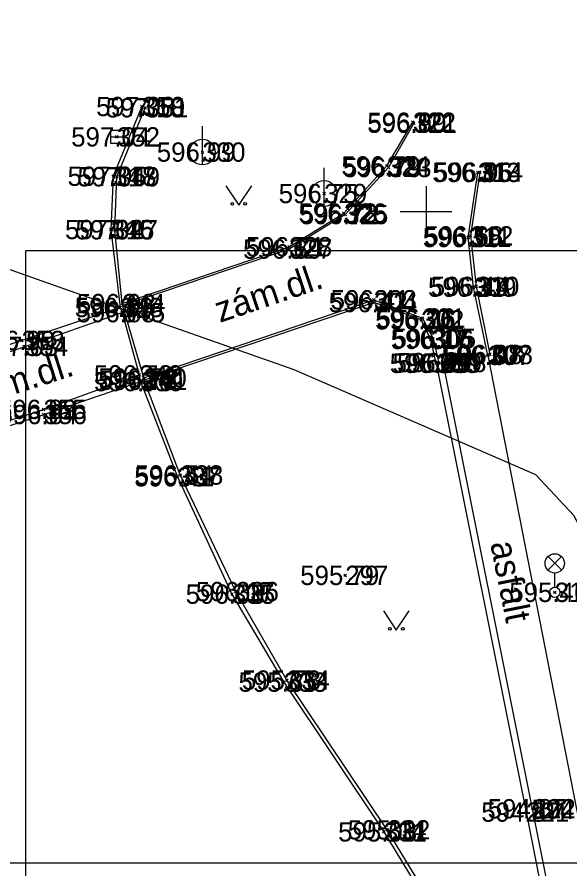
# Model space of a CAD drawing. Extents: x -844765 to -843273, y -997542 to -995529.
# Drawn here: x -843415.89 to -843394.41, y -997375.54 to -997342.43 of the extents above; entities that cross this region are included whole.
import ezdxf

# ---------------------------------------------------------------- set-up
doc = ezdxf.new("R2010")
doc.units = 0
for name, color, linetype in [('Betonový strop', 7, 'Continuous'), ('Dno', 7, 'Continuous'), ('Doplněk polohopisu', 7, 'Continuous'), ('Groma', 7, 'Continuous'), ('Osa', 7, 'Continuous'), ('Rámeček', 7, 'Continuous'), ('Sítě podzemní nerozlišené', 7, 'Continuous'), ('Vrstva 63', 7, 'Continuous'), ('Výška', 7, 'Continuous'), ('Číslo bodu', 7, 'Continuous'), ('Řezy', 7, 'Continuous')]:
    doc.layers.add(name, color=color, linetype=linetype)

msp = doc.modelspace()

# ---------------------------------------------------------------- linework, layer by layer
at = {"layer": 'Betonový strop'}
for p, q in [((-843399.33, -997355.86), (-843397.6, -997355.58)), ((-843397.6, -997355.58), (-843397.52, -997355.55))]:
    msp.add_line(p, q, dxfattribs=at)
for points in [[(-843411.04, -997345.91), (-843412.15, -997348.62), (-843412.25, -997350.69), (-843411.88, -997353.72), (-843411.81, -997353.92), (-843411.14, -997356.34), (-843411.1, -997356.6), (-843409.66, -997360.3), (-843407.54, -997364.86), (-843405.52, -997368.28), (-843401.64, -997374.1), (-843397.84, -997380.36), (-843394.46, -997387.21), (-843392.42, -997392.24)], [(-843392.47, -997391.81), (-843394.34, -997387.15), (-843397.7, -997380.27), (-843401.51, -997374.02), (-843405.41, -997368.2), (-843407.39, -997364.76), (-843409.55, -997360.23), (-843410.95, -997356.55), (-843410.97, -997356.46), (-843411.8, -997353.57), (-843412.09, -997350.7), (-843412.01, -997348.64), (-843410.91, -997345.96)], [(-843411.8, -997353.57), (-843405.32, -997351.36), (-843403.19, -997350.05), (-843401.52, -997348.22), (-843400.51, -997346.52)], [(-843400.48, -997346.56), (-843401.46, -997348.28), (-843403.14, -997350.11), (-843405.32, -997351.45), (-843411.778, -997353.647)], [(-843397.6, -997355.58), (-843398.16, -997352.93), (-843398.36, -997351), (-843397.99, -997348.47)], [(-843397.91, -997348.46), (-843398.28, -997350.94), (-843398.05, -997352.9), (-843397.52, -997355.55)], [(-843410.97, -997356.46), (-843402.03, -997353.42), (-843400.14, -997354.13), (-843399.73, -997354.92), (-843399.5, -997355.88)], [(-843399.61, -997355.89), (-843399.82, -997354.96), (-843400.19, -997354.2), (-843402.02, -997353.53), (-843410.95, -997356.55)], [(-843411.88, -997353.72), (-843415.71, -997355), (-843419.57, -997356.31)], [(-843419.54, -997356.54), (-843415.58, -997355.23), (-843411.81, -997353.92)], [(-843397.6, -997355.58), (-843394.16, -997373.22), (-843391.89, -997384.08), (-843391.57, -997385.85), (-843390.33, -997391.86), (-843386.25, -997412.31), (-843384.43, -997421.53), (-843384.06, -997423.53), (-843381.79, -997434.8)], [(-843399.61, -997355.89), (-843399.5, -997355.88), (-843399.33, -997355.86)], [(-843399.61, -997355.89), (-843396.11, -997373.33), (-843392.47, -997391.81), (-843392.42, -997392.24), (-843388.24, -997412.76), (-843386.27, -997422.84), (-843384.29, -997432.84)], [(-843384.04, -997432.8), (-843386.03, -997422.75), (-843388, -997412.68), (-843392.09, -997392.16), (-843395.86, -997373.2), (-843399.33, -997355.86)], [(-843418.65, -997358.89), (-843414.86, -997357.68), (-843411.14, -997356.34)], [(-843418.55, -997359.09), (-843414.85, -997357.88), (-843411.1, -997356.6)]]:
    msp.add_lwpolyline(points, dxfattribs=at)
at = {"layer": 'Dno'}
for points in [[(-843407.775, -997348.994), (-843407.275, -997349.744), (-843406.775, -997348.994)], [(-843401.655, -997365.509), (-843401.155, -997366.259), (-843400.655, -997365.509)]]:
    msp.add_lwpolyline(points, dxfattribs=at)
for centre in [(-843407.525, -997349.694), (-843407.025, -997349.694), (-843401.405, -997366.209), (-843400.905, -997366.209)]:
    msp.add_circle(centre, 0.05, dxfattribs=at)
at = {"layer": 'Doplněk polohopisu'}
for p, q in [((-843408.69, -997348.18), (-843408.69, -997346.68)), ((-843412.26, -997347.09), (-843411.76, -997347.09)), ((-843403.96, -997349.79), (-843403.96, -997348.29))]:
    msp.add_line(p, q, dxfattribs=at)
msp.add_lwpolyline([(-843412.26, -997347.34), (-843411.76, -997347.34), (-843411.76, -997346.84), (-843412.26, -997346.84)], close=True, dxfattribs=at)
for centre in [(-843408.69, -997347.68), (-843403.96, -997349.29)]:
    msp.add_circle(centre, 0.5, dxfattribs=at)
at = {"layer": 'Groma'}
for p, q in [((-843395.264, -997363.928), (-843394.736, -997363.4)), ((-843394.728, -997363.925), (-843395.256, -997363.396)), ((-843395, -997364.59), (-843395, -997364.04))]:
    msp.add_line(p, q, dxfattribs=at)
for centre, radius in [((-843395, -997363.665), 0.375), ((-843395, -997364.79), 0.2)]:
    msp.add_circle(centre, radius, dxfattribs=at)
at = {"layer": 'Osa'}
msp.add_lwpolyline([(-843361.41, -997525.395), (-843362.635, -997520.015), (-843367.895, -997475.79), (-843371.92, -997453.18), (-843393.72, -997362.81), (-843394.265, -997361.8), (-843395.735, -997360.23), (-843405.12, -997356.145), (-843414.51, -997352.845), (-843426.28, -997348.668), (-843434.95, -997345.635), (-843447.93, -997341.273), (-843467.555, -997334.81), (-843481.31, -997330.35), (-843488.74, -997327.355), (-843502.42, -997320.345)], dxfattribs=at)
at = {"layer": 'Rámeček'}
for p, q in [((-843400, -997349), (-843400, -997351)), ((-843399, -997350), (-843401, -997350))]:
    msp.add_line(p, q, dxfattribs=at)
at = {"layer": 'Sítě podzemní nerozlišené'}
for p, q in [((-843411.04, -997345.91), (-843411.09, -997345.86)), ((-843411.04, -997345.91), (-843411.09, -997345.96)), ((-843411.04, -997345.91), (-843410.99, -997345.86)), ((-843411.04, -997345.91), (-843410.99, -997345.96)), ((-843410.91, -997345.96), (-843410.96, -997345.91)), ((-843410.91, -997345.96), (-843410.86, -997345.91)), ((-843410.91, -997345.96), (-843410.96, -997346.01)), ((-843410.91, -997345.96), (-843410.86, -997346.01)), ((-843400.51, -997346.52), (-843400.56, -997346.47)), ((-843400.51, -997346.52), (-843400.56, -997346.57)), ((-843400.48, -997346.56), (-843400.53, -997346.51)), ((-843400.48, -997346.56), (-843400.53, -997346.61)), ((-843400.51, -997346.52), (-843400.46, -997346.47)), ((-843400.51, -997346.52), (-843400.46, -997346.57)), ((-843400.48, -997346.56), (-843400.43, -997346.51)), ((-843400.48, -997346.56), (-843400.43, -997346.61)), ((-843412.01, -997347.09), (-843412.06, -997347.04)), ((-843412.01, -997347.09), (-843412.06, -997347.14)), ((-843412.01, -997347.09), (-843411.96, -997347.04)), ((-843412.01, -997347.09), (-843411.96, -997347.14)), ((-843408.69, -997347.68), (-843408.74, -997347.63)), ((-843408.69, -997347.68), (-843408.74, -997347.73)), ((-843408.69, -997347.68), (-843408.64, -997347.63)), ((-843408.69, -997347.68), (-843408.64, -997347.73)), ((-843401.52, -997348.22), (-843401.57, -997348.17)), ((-843401.52, -997348.22), (-843401.57, -997348.27)), ((-843401.52, -997348.22), (-843401.47, -997348.17)), ((-843401.52, -997348.22), (-843401.47, -997348.27)), ((-843401.46, -997348.28), (-843401.51, -997348.23)), ((-843401.46, -997348.28), (-843401.41, -997348.23)), ((-843401.46, -997348.28), (-843401.51, -997348.33)), ((-843401.46, -997348.28), (-843401.41, -997348.33)), ((-843397.99, -997348.47), (-843398.04, -997348.42)), ((-843397.99, -997348.47), (-843398.04, -997348.52)), ((-843397.99, -997348.47), (-843397.94, -997348.42)), ((-843397.99, -997348.47), (-843397.94, -997348.52)), ((-843397.91, -997348.46), (-843397.96, -997348.41)), ((-843397.91, -997348.46), (-843397.96, -997348.51)), ((-843397.91, -997348.46), (-843397.86, -997348.41)), ((-843397.91, -997348.46), (-843397.86, -997348.51)), ((-843412.15, -997348.62), (-843412.2, -997348.57)), ((-843412.15, -997348.62), (-843412.2, -997348.67)), ((-843412.15, -997348.62), (-843412.1, -997348.57)), ((-843412.15, -997348.62), (-843412.1, -997348.67)), ((-843412.01, -997348.64), (-843412.06, -997348.59)), ((-843412.01, -997348.64), (-843412.06, -997348.69)), ((-843412.01, -997348.64), (-843411.96, -997348.59)), ((-843412.01, -997348.64), (-843411.96, -997348.69)), ((-843403.96, -997349.29), (-843404.01, -997349.24)), ((-843403.96, -997349.29), (-843404.01, -997349.34)), ((-843403.96, -997349.29), (-843403.91, -997349.24)), ((-843403.96, -997349.29), (-843403.91, -997349.34)), ((-843403.19, -997350.05), (-843403.24, -997350)), ((-843403.19, -997350.05), (-843403.24, -997350.1)), ((-843403.19, -997350.05), (-843403.14, -997350)), ((-843403.19, -997350.05), (-843403.14, -997350.1)), ((-843403.14, -997350.11), (-843403.19, -997350.06)), ((-843403.14, -997350.11), (-843403.19, -997350.16)), ((-843403.14, -997350.11), (-843403.09, -997350.06)), ((-843403.14, -997350.11), (-843403.09, -997350.16)), ((-843412.25, -997350.69), (-843412.3, -997350.64)), ((-843412.25, -997350.69), (-843412.3, -997350.74)), ((-843412.25, -997350.69), (-843412.2, -997350.64)), ((-843412.25, -997350.69), (-843412.2, -997350.74)), ((-843412.09, -997350.7), (-843412.14, -997350.65)), ((-843412.09, -997350.7), (-843412.14, -997350.75)), ((-843412.09, -997350.7), (-843412.04, -997350.65)), ((-843412.09, -997350.7), (-843412.04, -997350.75)), ((-843398.36, -997351), (-843398.41, -997350.95)), ((-843398.36, -997351), (-843398.41, -997351.05)), ((-843398.36, -997351), (-843398.31, -997350.95)), ((-843398.36, -997351), (-843398.31, -997351.05)), ((-843398.28, -997350.94), (-843398.33, -997350.89)), ((-843398.28, -997350.94), (-843398.33, -997350.99)), ((-843398.28, -997350.94), (-843398.23, -997350.89)), ((-843398.28, -997350.94), (-843398.23, -997350.99)), ((-843405.32, -997351.36), (-843405.37, -997351.31)), ((-843405.32, -997351.36), (-843405.37, -997351.41)), ((-843405.32, -997351.45), (-843405.37, -997351.4)), ((-843405.32, -997351.45), (-843405.37, -997351.5)), ((-843405.32, -997351.36), (-843405.27, -997351.31)), ((-843405.32, -997351.36), (-843405.27, -997351.41)), ((-843405.32, -997351.45), (-843405.27, -997351.4)), ((-843405.32, -997351.45), (-843405.27, -997351.5)), ((-843398.05, -997352.9), (-843398.1, -997352.85)), ((-843398.05, -997352.9), (-843398, -997352.85)), ((-843398.16, -997352.93), (-843398.21, -997352.88)), ((-843398.16, -997352.93), (-843398.21, -997352.98)), ((-843398.16, -997352.93), (-843398.11, -997352.88)), ((-843398.16, -997352.93), (-843398.11, -997352.98)), ((-843398.05, -997352.9), (-843398.1, -997352.95)), ((-843398.05, -997352.9), (-843398, -997352.95)), ((-843411.8, -997353.57), (-843411.85, -997353.52)), ((-843411.8, -997353.57), (-843411.75, -997353.52)), ((-843402.03, -997353.42), (-843402.08, -997353.37)), ((-843402.03, -997353.42), (-843402.08, -997353.47)), ((-843402.02, -997353.53), (-843402.07, -997353.48)), ((-843402.02, -997353.53), (-843402.07, -997353.58)), ((-843402.03, -997353.42), (-843401.98, -997353.37)), ((-843402.03, -997353.42), (-843401.98, -997353.47)), ((-843402.02, -997353.53), (-843401.97, -997353.48)), ((-843402.02, -997353.53), (-843401.97, -997353.58)), ((-843411.88, -997353.72), (-843411.93, -997353.67)), ((-843411.88, -997353.72), (-843411.93, -997353.77)), ((-843411.88, -997353.72), (-843411.83, -997353.67)), ((-843411.88, -997353.72), (-843411.83, -997353.77)), ((-843411.8, -997353.57), (-843411.85, -997353.62)), ((-843411.8, -997353.57), (-843411.75, -997353.62)), ((-843411.81, -997353.92), (-843411.86, -997353.87)), ((-843411.81, -997353.92), (-843411.86, -997353.97)), ((-843411.81, -997353.92), (-843411.76, -997353.87)), ((-843411.81, -997353.92), (-843411.76, -997353.97)), ((-843400.19, -997354.2), (-843400.24, -997354.15)), ((-843400.14, -997354.13), (-843400.19, -997354.08)), ((-843400.14, -997354.13), (-843400.19, -997354.18)), ((-843400.19, -997354.2), (-843400.14, -997354.15)), ((-843400.14, -997354.13), (-843400.09, -997354.08)), ((-843400.14, -997354.13), (-843400.09, -997354.18)), ((-843400.19, -997354.2), (-843400.24, -997354.25)), ((-843400.19, -997354.2), (-843400.14, -997354.25)), ((-843415.71, -997355), (-843415.76, -997354.95)), ((-843415.71, -997355), (-843415.76, -997355.05)), ((-843415.71, -997355), (-843415.66, -997354.95)), ((-843415.71, -997355), (-843415.66, -997355.05)), ((-843415.58, -997355.23), (-843415.63, -997355.18)), ((-843415.58, -997355.23), (-843415.53, -997355.18)), ((-843399.82, -997354.96), (-843399.87, -997354.91)), ((-843399.82, -997354.96), (-843399.87, -997355.01)), ((-843399.82, -997354.96), (-843399.77, -997354.91)), ((-843399.82, -997354.96), (-843399.77, -997355.01)), ((-843399.73, -997354.92), (-843399.78, -997354.87)), ((-843399.73, -997354.92), (-843399.78, -997354.97)), ((-843399.73, -997354.92), (-843399.68, -997354.87)), ((-843399.73, -997354.92), (-843399.68, -997354.97)), ((-843415.58, -997355.23), (-843415.63, -997355.28)), ((-843415.58, -997355.23), (-843415.53, -997355.28)), ((-843397.52, -997355.55), (-843397.57, -997355.5)), ((-843397.52, -997355.55), (-843397.47, -997355.5)), ((-843399.61, -997355.89), (-843399.66, -997355.84)), ((-843399.61, -997355.89), (-843399.56, -997355.84)), ((-843399.5, -997355.88), (-843399.55, -997355.83)), ((-843399.5, -997355.88), (-843399.45, -997355.83)), ((-843399.33, -997355.86), (-843399.38, -997355.81)), ((-843399.33, -997355.86), (-843399.28, -997355.81)), ((-843397.6, -997355.58), (-843397.65, -997355.53)), ((-843397.6, -997355.58), (-843397.65, -997355.63)), ((-843397.6, -997355.58), (-843397.55, -997355.53)), ((-843397.6, -997355.58), (-843397.55, -997355.63)), ((-843397.52, -997355.55), (-843397.57, -997355.6)), ((-843397.52, -997355.55), (-843397.47, -997355.6)), ((-843399.61, -997355.89), (-843399.66, -997355.94)), ((-843399.61, -997355.89), (-843399.56, -997355.94)), ((-843399.5, -997355.88), (-843399.55, -997355.93)), ((-843399.5, -997355.88), (-843399.45, -997355.93)), ((-843399.33, -997355.86), (-843399.38, -997355.91)), ((-843399.33, -997355.86), (-843399.28, -997355.91)), ((-843411.14, -997356.34), (-843411.19, -997356.29)), ((-843411.14, -997356.34), (-843411.19, -997356.39)), ((-843411.14, -997356.34), (-843411.09, -997356.29)), ((-843411.14, -997356.34), (-843411.09, -997356.39)), ((-843410.97, -997356.46), (-843411.02, -997356.41)), ((-843410.97, -997356.46), (-843411.02, -997356.51)), ((-843410.95, -997356.55), (-843411, -997356.5)), ((-843410.97, -997356.46), (-843410.92, -997356.41)), ((-843410.97, -997356.46), (-843410.92, -997356.51)), ((-843410.95, -997356.55), (-843410.9, -997356.5)), ((-843411.1, -997356.6), (-843411.15, -997356.55)), ((-843411.1, -997356.6), (-843411.15, -997356.65)), ((-843411.1, -997356.6), (-843411.05, -997356.55)), ((-843411.1, -997356.6), (-843411.05, -997356.65)), ((-843410.95, -997356.55), (-843411, -997356.6)), ((-843410.95, -997356.55), (-843410.9, -997356.6)), ((-843414.86, -997357.68), (-843414.91, -997357.63)), ((-843414.86, -997357.68), (-843414.91, -997357.73)), ((-843414.85, -997357.88), (-843414.9, -997357.83)), ((-843414.86, -997357.68), (-843414.81, -997357.63)), ((-843414.86, -997357.68), (-843414.81, -997357.73)), ((-843414.85, -997357.88), (-843414.8, -997357.83)), ((-843414.85, -997357.88), (-843414.9, -997357.93)), ((-843414.85, -997357.88), (-843414.8, -997357.93)), ((-843409.66, -997360.3), (-843409.71, -997360.25)), ((-843409.66, -997360.3), (-843409.71, -997360.35)), ((-843409.66, -997360.3), (-843409.61, -997360.25)), ((-843409.66, -997360.3), (-843409.61, -997360.35)), ((-843409.55, -997360.23), (-843409.6, -997360.18)), ((-843409.55, -997360.23), (-843409.6, -997360.28)), ((-843409.55, -997360.23), (-843409.5, -997360.18)), ((-843409.55, -997360.23), (-843409.5, -997360.28)), ((-843403.14, -997364.13), (-843403.19, -997364.08)), ((-843403.14, -997364.13), (-843403.09, -997364.08)), ((-843403.14, -997364.13), (-843403.19, -997364.18)), ((-843403.14, -997364.13), (-843403.09, -997364.18)), ((-843407.39, -997364.76), (-843407.44, -997364.71)), ((-843407.39, -997364.76), (-843407.44, -997364.81)), ((-843407.39, -997364.76), (-843407.34, -997364.71)), ((-843407.39, -997364.76), (-843407.34, -997364.81)), ((-843395, -997364.79), (-843395.05, -997364.74)), ((-843395, -997364.79), (-843394.95, -997364.74)), ((-843407.54, -997364.86), (-843407.59, -997364.81)), ((-843407.54, -997364.86), (-843407.59, -997364.91)), ((-843407.54, -997364.86), (-843407.49, -997364.81)), ((-843407.54, -997364.86), (-843407.49, -997364.91)), ((-843395, -997364.79), (-843395.05, -997364.84)), ((-843395, -997364.79), (-843394.95, -997364.84)), ((-843405.52, -997368.28), (-843405.57, -997368.23)), ((-843405.52, -997368.28), (-843405.57, -997368.33)), ((-843405.52, -997368.28), (-843405.47, -997368.23)), ((-843405.52, -997368.28), (-843405.47, -997368.33)), ((-843405.41, -997368.2), (-843405.46, -997368.15)), ((-843405.41, -997368.2), (-843405.46, -997368.25)), ((-843405.41, -997368.2), (-843405.36, -997368.15)), ((-843405.41, -997368.2), (-843405.36, -997368.25)), ((-843396.11, -997373.33), (-843396.16, -997373.28)), ((-843396.11, -997373.33), (-843396.16, -997373.38)), ((-843396.11, -997373.33), (-843396.06, -997373.28)), ((-843396.11, -997373.33), (-843396.06, -997373.38)), ((-843395.86, -997373.2), (-843395.91, -997373.15)), ((-843395.86, -997373.2), (-843395.91, -997373.25)), ((-843395.86, -997373.2), (-843395.81, -997373.15)), ((-843395.86, -997373.2), (-843395.81, -997373.25)), ((-843401.64, -997374.1), (-843401.69, -997374.05)), ((-843401.64, -997374.1), (-843401.59, -997374.05)), ((-843401.51, -997374.02), (-843401.56, -997373.97)), ((-843401.51, -997374.02), (-843401.56, -997374.07)), ((-843401.51, -997374.02), (-843401.46, -997373.97)), ((-843401.51, -997374.02), (-843401.46, -997374.07)), ((-843401.64, -997374.1), (-843401.69, -997374.15)), ((-843401.64, -997374.1), (-843401.59, -997374.15))]:
    msp.add_line(p, q, dxfattribs=at)
at = {"layer": 'Vrstva 63'}
for points in [[(-843572.683, -997375.3), (-843382.683, -997375.3), (-843382.683, -997232.8), (-843572.683, -997232.8)], [(-843273.067, -997541.514), (-843273.067, -997351.514), (-843415.567, -997351.514), (-843415.567, -997541.514)]]:
    msp.add_lwpolyline(points, close=True, dxfattribs=at)

# ---------------------------------------------------------------- texts
at = {"layer": 'Výška'}
for s, rotation, p in [('zám.dl.', 18.6848, (-843408.012, -997354.321)), ('zám.dl.', 17.7063, (-843417.721, -997357.656)), ('asfalt', 281.3163, (-843397.511, -997362.885))]:
    msp.add_text(s, height=1, rotation=rotation, dxfattribs=at).set_placement(p)
at = {"layer": 'Číslo bodu'}
for s, p in [('350', (-843411.04, -997346.285)), ('351', (-843410.91, -997346.335)), ('322', (-843400.51, -997346.895)), ('321', (-843400.48, -997346.935)), ('352', (-843412.01, -997347.465)), ('330', (-843408.69, -997348.055)), ('324', (-843401.52, -997348.595)), ('323', (-843401.46, -997348.655)), ('348', (-843412.15, -997348.995)), ('313', (-843397.99, -997348.845)), ('314', (-843397.91, -997348.835)), ('349', (-843412.01, -997349.015)), ('329', (-843403.96, -997349.665)), ('326', (-843403.19, -997350.425)), ('325', (-843403.14, -997350.485)), ('346', (-843412.25, -997351.065)), ('347', (-843412.09, -997351.075)), ('311', (-843398.36, -997351.375)), ('312', (-843398.28, -997351.315)), ('328', (-843405.32, -997351.735)), ('327', (-843405.32, -997351.825)), ('310', (-843398.05, -997353.275)), ('309', (-843398.16, -997353.305)), ('344', (-843411.8, -997353.945)), ('303', (-843402.03, -997353.795)), ('304', (-843402.02, -997353.905)), ('343', (-843411.88, -997354.095)), ('345', (-843411.81, -997354.295)), ('302', (-843400.19, -997354.575)), ('301', (-843400.14, -997354.505)), ('353', (-843415.71, -997355.375)), ('354', (-843415.58, -997355.605)), ('306', (-843399.82, -997355.335)), ('305', (-843399.73, -997355.295)), ('308', (-843397.52, -997355.925)), ('300', (-843399.61, -997356.265)), ('299', (-843399.5, -997356.255)), ('298', (-843399.33, -997356.235)), ('307', (-843397.6, -997355.955)), ('342', (-843411.14, -997356.715)), ('340', (-843410.97, -997356.835)), ('341', (-843410.95, -997356.925)), ('339', (-843411.1, -997356.975)), ('355', (-843414.86, -997358.055)), ('356', (-843414.85, -997358.255)), ('337', (-843409.66, -997360.675)), ('338', (-843409.55, -997360.605)), ('297', (-843403.14, -997364.505)), ('336', (-843407.39, -997365.135)), ('319', (-843395, -997365.165)), ('335', (-843407.54, -997365.235)), ('333', (-843405.52, -997368.655)), ('334', (-843405.41, -997368.575)), ('221', (-843396.11, -997373.705)), ('222', (-843395.86, -997373.575)), ('331', (-843401.64, -997374.475)), ('332', (-843401.51, -997374.395))]:
    msp.add_text(s, height=0.75, dxfattribs=at).set_placement(p)
at = {"layer": 'Řezy'}
for s, p in [('597.08', (-843412.817, -997346.285)), ('597.18', (-843412.442, -997346.335)), ('596.90', (-843402.281, -997346.935)), ('596.89', (-843402.279, -997346.895)), ('597.04', (-843413.787, -997347.465)), ('596.99', (-843410.461, -997348.055)), ('596.79', (-843403.289, -997348.595)), ('596.79', (-843403.229, -997348.655)), ('597.05', (-843413.927, -997348.995)), ('596.85', (-843399.756, -997348.845)), ('596.96', (-843399.699, -997348.835)), ('597.17', (-843413.542, -997349.015)), ('596.75', (-843405.726, -997349.665)), ('596.73', (-843404.956, -997350.425)), ('596.72', (-843404.906, -997350.485)), ('597.02', (-843414.027, -997351.065)), ('597.15', (-843413.622, -997351.075)), ('596.59', (-843400.129, -997351.375)), ('596.68', (-843400.066, -997351.315)), ('596.69', (-843407.109, -997351.825)), ('596.71', (-843406.997, -997351.735)), ('596.44', (-843399.816, -997353.275)), ('596.33', (-843399.926, -997353.305)), ('596.92', (-843413.569, -997353.945)), ('596.42', (-843403.786, -997353.905)), ('596.41', (-843403.707, -997353.795)), ('596.89', (-843413.649, -997354.095)), ('596.88', (-843413.576, -997354.295)), ('596.26', (-843401.976, -997354.575)), ('596.26', (-843401.926, -997354.505)), ('596.99', (-843417.481, -997355.375)), ('597.03', (-843417.357, -997355.605)), ('596.17', (-843401.373, -997355.335)), ('596.16', (-843401.304, -997355.295)), ('596.08', (-843399.318, -997355.925)), ('596.09', (-843401.411, -997356.265)), ('596.09', (-843401.301, -997356.255)), ('596.07', (-843401.128, -997356.235)), ('596.07', (-843399.398, -997355.955)), ('596.73', (-843412.906, -997356.715)), ('596.72', (-843412.736, -997356.835)), ('596.73', (-843412.716, -997356.925)), ('596.70', (-843412.898, -997356.975)), ('596.89', (-843416.629, -997358.055)), ('596.84', (-843416.616, -997358.255)), ('596.41', (-843411.337, -997360.675)), ('596.54', (-843411.316, -997360.605)), ('595.79', (-843404.888, -997364.505)), ('596.17', (-843408.943, -997365.135)), ('595.46', (-843396.766, -997365.165)), ('596.03', (-843409.338, -997365.235)), ('595.65', (-843407.286, -997368.655)), ('595.78', (-843407.155, -997368.575)), ('594.87', (-843397.855, -997373.705)), ('594.87', (-843397.605, -997373.575)), ('594.87', (-843395.905, -997373.595)), ('595.03', (-843403.417, -997374.475)), ('595.14', (-843403.042, -997374.395))]:
    msp.add_text(s, height=0.75, dxfattribs=at).set_placement(p)

doc.saveas('drawing.dxf')
